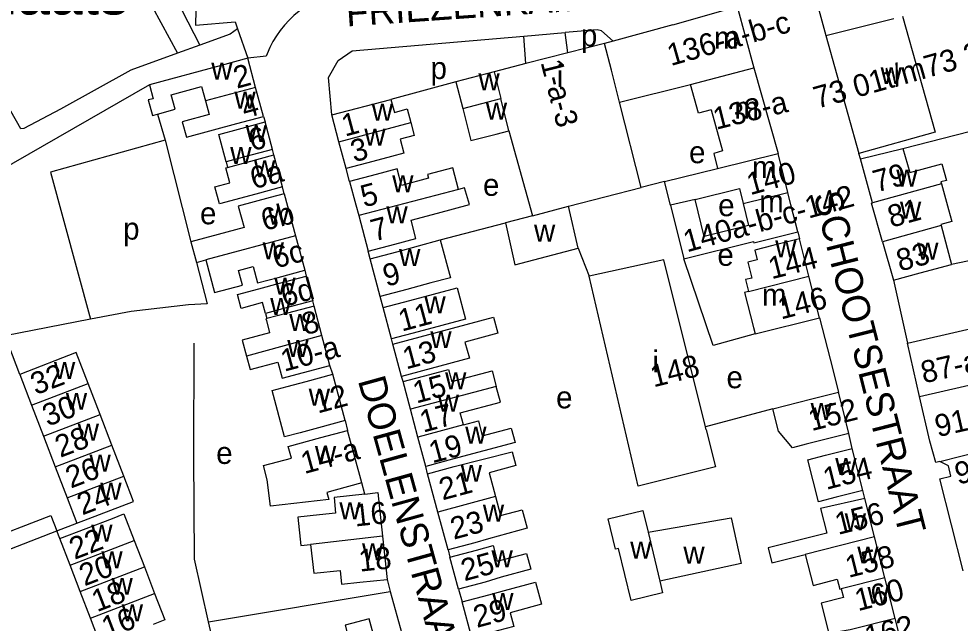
# Model space of a CAD drawing. Extents: x 159261 to 160849, y 382514 to 384534.
# Drawn here: x 159592.3 to 159763.1, y 383674.1 to 383783.7 of the extents above; entities that cross this region are included whole.
import ezdxf

# ---------------------------------------------------------------- set-up
doc = ezdxf.new("R2010")
doc.units = 0
for name, color, linetype in [('BLT_Basislijn', 7, 'Continuous'), ('BLT_Bebouwing', 7, 'Continuous'), ('BLT_Centroide', 7, 'Continuous'), ('BLT_Huisnummer', 7, 'Continuous'), ('BLT_Huisnummer_ tussenligend', 7, 'Continuous'), ('BLT_Huisnummer_reeks', 7, 'Continuous'), ('BLT_Onderdoorgang_en_onderverdeling', 7, 'Continuous'), ('BLT_Onderverdeling_panden', 7, 'Continuous'), ('BLT_Straatnaam', 7, 'Continuous'), ('BLT_Terrein_beschrifting', 7, 'Continuous')]:
    doc.layers.add(name, color=color, linetype=linetype)

msp = doc.modelspace()

# ---------------------------------------------------------------- linework, layer by layer
at = {"layer": 'BLT_Basislijn'}
for p, q in [((159631.56, 383783.16), (159631.95, 383781.91)), ((159631.95, 383781.91), (159633.83, 383776.57)), ((159683.95, 383780.59), (159691.46, 383781.26)), ((159684.27, 383775.61), (159683.95, 383780.59)), ((159691.94, 383777.56), (159691.46, 383781.26)), ((159625.16, 383778.96), (159621.07, 383777.49)), ((159637.2, 383776.98), (159633.83, 383776.57)), ((159671.62, 383772.28), (159659.82, 383769.08)), ((159616.02, 383771.76), (159555.43, 383737.07)), ((159617.49, 383766.46), (159618.85, 383761.7)), ((159636.68, 383766.03), (159636.97, 383765.02)), ((159618.85, 383761.7), (159598.02, 383755.92)), ((159618.85, 383761.7), (159623.53, 383743.27)), ((159745.03, 383758.31), (159744.75, 383759.29)), ((159598.02, 383755.92), (159605.29, 383729.24)), ((159652.31, 383754.2), (159651.68, 383756.56)), ((159640.44, 383752), (159640.14, 383753.25)), ((159709.46, 383754.23), (159705.24, 383753.14)), ((159668.75, 383743.65), (159680.58, 383746.7)), ((159733.64, 383745.1), (159733.95, 383743.83)), ((159656.04, 383740.19), (159655.71, 383741.59)), ((159773.27, 383741.61), (159761.57, 383739.18)), ((159644.17, 383738.12), (159644.42, 383737.08)), ((159751, 383736.32), (159753.55, 383724.92)), ((159658.41, 383731.34), (159657.87, 383733.36)), ((159737.57, 383729.51), (159739.51, 383721.98)), ((159592.46, 383719.24), (159589.8, 383726.24)), ((159624.03, 383704.44), (159624.09, 383724.91)), ((159660.18, 383724.73), (159659.93, 383725.66)), ((159649.27, 383719.25), (159648.76, 383720.87)), ((159739.51, 383721.98), (159741.04, 383716.02)), ((159662.02, 383717.93), (159661.75, 383718.87)), ((159729.11, 383713), (159716.91, 383709.74)), ((159651.52, 383710.84), (159651.91, 383709.07)), ((159743.51, 383705.78), (159742.94, 383708.53)), ((159666.47, 383701.22), (159666.15, 383702.53)), ((159655.06, 383697.53), (159654.53, 383699.54)), ((159745.83, 383696.7), (159745.43, 383698.17)), ((159599.2, 383690.85), (159602.83, 383692.24)), ((159586.61, 383686.01), (159599.2, 383690.85)), ((159599.75, 383689.45), (159599.2, 383690.85)), ((159670.2, 383687.38), (159670.53, 383686.06)), ((159659.12, 383682.04), (159659.71, 383679.86)), ((159626.72, 383674.34), (159659.71, 383679.86)), ((159659.71, 383679.86), (159661.77, 383672.22)), ((159672.09, 383680.26), (159672.75, 383677.95)), ((159629.57, 383662.47), (159626.72, 383674.34))]:
    msp.add_line(p, q, dxfattribs=at)
for points in [[(159593.57, 383838.89), (159614.31, 383800.04), (159625.16, 383778.96)], [(159621.07, 383777.49), (159612.6, 383774.43), (159599.83, 383767.32), (159593.2, 383763.82), (159592.64, 383763.8), (159578.88, 383788.08), (159578.47, 383789.32), (159580.38, 383790.74), (159605.05, 383805.54), (159605.98, 383805.38), (159621.07, 383777.49)], [(159624.74, 383798.83), (159624.33, 383782.58), (159631.56, 383783.16)], [(159647.32, 383787.59), (159646.21, 383787.07), (159645.15, 383786.49), (159644.12, 383785.84), (159643.14, 383785.11), (159642.21, 383784.33), (159641.33, 383783.49), (159640.5, 383782.59), (159639.74, 383781.64), (159639.05, 383780.64), (159638.41, 383779.6), (159637.85, 383778.52), (159637.37, 383777.4), (159637.2, 383776.98)], [(159631.95, 383781.91), (159630.64, 383780.98), (159625.16, 383778.96)], [(159649.08, 383766.33), (159648.52, 383773.07), (159650.27, 383776.15), (159652.81, 383777.91), (159683.95, 383780.59)], [(159700.15, 383779.66), (159698.06, 383781.54), (159697.23, 383781.74), (159691.46, 383781.26)], [(159752.73, 383760.22), (159784.09, 383768.23), (159781.95, 383775.97), (159783.82, 383776.48), (159786.45, 383777.94), (159787.98, 383780.15)], [(159693.78, 383742.14), (159695.8, 383737.05)], [(159725.91, 383726.57), (159718.32, 383724.47), (159712.99, 383740.18)], [(159624.53, 383739.56), (159626.5, 383732.04), (159623.07, 383731.83), (159612.69, 383730.67)], [(159612.69, 383730.67), (159605.29, 383729.24)], [(159605.29, 383729.24), (159589.8, 383726.24)], [(159626.72, 383674.34), (159624.2, 383685.7), (159624.03, 383704.44)], [(159585.55, 383688.82), (159598.13, 383693.65), (159599.2, 383690.85)]]:
    msp.add_lwpolyline(points, dxfattribs=at)
at = {"layer": 'BLT_Bebouwing'}
for p, q in [((159711, 383782.62), (159700.15, 383779.66)), ((159698.59, 383779.26), (159691.94, 383777.56)), ((159700.15, 383779.66), (159698.59, 383779.26)), ((159691.94, 383777.56), (159684.27, 383775.61)), ((159635.25, 383771.3), (159633.83, 383776.57)), ((159684.27, 383775.61), (159678.54, 383774.1)), ((159678.54, 383774.1), (159671.62, 383772.28)), ((159725.7, 383774.82), (159730.07, 383759.31)), ((159635.25, 383771.3), (159626.17, 383768.84)), ((159636.68, 383766.03), (159635.25, 383771.3)), ((159701.3, 383768.62), (159714.21, 383771.84)), ((159649.08, 383766.33), (159659.82, 383769.08)), ((159705.24, 383753.14), (159701.3, 383768.62)), ((159650.38, 383761.45), (159649.08, 383766.33)), ((159638.32, 383760.06), (159636.97, 383765.02)), ((159681.23, 383763.43), (159685.49, 383748.01)), ((159651.68, 383756.56), (159650.38, 383761.45)), ((159745.03, 383758.31), (159752.73, 383760.22)), ((159638.57, 383759.06), (159638.32, 383760.06)), ((159640.14, 383753.25), (159638.57, 383759.06)), ((159731.84, 383752.25), (159730.07, 383759.31)), ((159629.91, 383757.78), (159630.17, 383756.79)), ((159747.18, 383750.35), (159745.03, 383758.31)), ((159709.46, 383754.23), (159719.08, 383756.57)), ((159640.44, 383752), (159642.49, 383744.38)), ((159692.05, 383749.76), (159705.24, 383753.14)), ((159710.53, 383749.96), (159712.99, 383740.18)), ((159693.78, 383742.14), (159692.05, 383749.76)), ((159653.97, 383748.08), (159655.71, 383741.59)), ((159685.49, 383748.01), (159680.58, 383746.7)), ((159759.67, 383746.22), (159761.57, 383739.18)), ((159623.53, 383743.27), (159624.53, 383739.56)), ((159642.49, 383744.38), (159644.17, 383738.12)), ((159735.66, 383737.07), (159733.95, 383743.83)), ((159749.02, 383743.29), (159751, 383736.32)), ((159624.53, 383739.56), (159626.24, 383740.02)), ((159657.87, 383733.36), (159656.04, 383740.19)), ((159644.42, 383737.08), (159645.62, 383732.59)), ((159737.57, 383729.51), (159735.66, 383737.07)), ((159645.87, 383731.64), (159645.62, 383732.59)), ((159647.31, 383726.26), (159645.87, 383731.64)), ((159659.93, 383725.66), (159658.41, 383731.34)), ((159637.07, 383730.29), (159637.32, 383729.35)), ((159725.91, 383726.57), (159737.57, 383729.51)), ((159648.76, 383720.87), (159647.31, 383726.26)), ((159661.75, 383718.87), (159660.18, 383724.73)), ((159755.76, 383715.2), (159753.55, 383724.92)), ((159651.52, 383710.84), (159649.27, 383719.25)), ((159663.37, 383712.9), (159662.02, 383717.93)), ((159741.99, 383712.28), (159741.04, 383716.02)), ((159757.61, 383707.14), (159755.76, 383715.2)), ((159664.72, 383707.85), (159663.37, 383712.9)), ((159742.94, 383708.53), (159741.99, 383712.28)), ((159654.53, 383699.54), (159651.91, 383709.07)), ((159717.05, 383709.18), (159716.91, 383709.74)), ((159666.15, 383702.53), (159664.72, 383707.85)), ((159745.43, 383698.17), (159743.51, 383705.78)), ((159668.35, 383694.26), (159666.47, 383701.22)), ((159747.58, 383689.75), (159745.83, 383696.7)), ((159670.2, 383687.38), (159668.35, 383694.26)), ((159613.24, 383689.11), (159615.09, 383684.31)), ((159658.29, 383689.91), (159659.12, 383682.04)), ((159749.45, 383682.35), (159747.58, 383689.75)), ((159672.09, 383680.26), (159670.53, 383686.06)), ((159615.09, 383684.31), (159616.94, 383679.5)), ((159751.32, 383674.94), (159749.45, 383682.35)), ((159674.5, 383671.45), (159672.75, 383677.95)), ((159752.98, 383668.39), (159751.32, 383674.94))]:
    msp.add_line(p, q, dxfattribs=at)
for points in [[(159749.03, 383794.41), (159735.94, 383790.98), (159738.76, 383780.69)], [(159711, 383782.62), (159722.66, 383785.95), (159725.7, 383774.82)], [(159752.68, 383784.21), (159758.58, 383763.16), (159744.75, 383759.29)], [(159738.76, 383780.69), (159744.75, 383759.29)], [(159633.83, 383776.57), (159629, 383775.27), (159616.02, 383771.76)], [(159671.62, 383772.28), (159672.85, 383767.45)], [(159616.02, 383771.76), (159616.69, 383769.25), (159615.78, 383769.01), (159616.54, 383766.21), (159617.49, 383766.46)], [(159617.49, 383766.46), (159620.65, 383767.32), (159619.94, 383769.94), (159625.47, 383771.44), (159626.17, 383768.84)], [(159717.94, 383767.25), (159715.65, 383766.61), (159714.21, 383771.84)], [(159626.17, 383768.84), (159626.85, 383766.35), (159621.96, 383765.03), (159622.71, 383762.28), (159631.85, 383764.72), (159636.68, 383766.03)], [(159659.82, 383769.08), (159660.44, 383766.76), (159662.76, 383767.38), (159663.41, 383764.92)], [(159672.85, 383767.45), (159674.33, 383761.65), (159678.89, 383762.83)], [(159717.94, 383767.25), (159720.01, 383759.76), (159718.39, 383759.3)], [(159629.91, 383757.78), (159628.56, 383762.74), (159632.15, 383763.71), (159636.97, 383765.02)], [(159663.41, 383764.92), (159664.04, 383762.56), (159661.51, 383761.88), (159662.18, 383759.36), (159659.93, 383758.76), (159656.52, 383757.85), (159651.68, 383756.56)], [(159678.89, 383762.83), (159681.23, 383763.43)], [(159752.73, 383760.22), (159753.97, 383755.85), (159759.79, 383757.4), (159760.62, 383754.38), (159759.62, 383754.18), (159759.72, 383753.8)], [(159718.39, 383759.3), (159719.08, 383756.57)], [(159640.14, 383753.25), (159635.31, 383751.95), (159628.73, 383750.16), (159627.89, 383753.25), (159630.57, 383753.97), (159629.83, 383756.7), (159630.17, 383756.79)], [(159672.09, 383752.76), (159671.03, 383756.71), (159666.44, 383755.47), (159666.61, 383754.81), (159661.74, 383753.51), (159660.94, 383756.51), (159657.14, 383755.49), (159652.31, 383754.2)], [(159652.31, 383754.2), (159653.45, 383750), (159653.97, 383748.08)], [(159710.53, 383749.96), (159709.46, 383754.23)], [(159759.72, 383753.8), (159760.99, 383749.16), (159761.59, 383746.94), (159759.62, 383746.4), (159759.67, 383746.22)], [(159640.44, 383752), (159637.93, 383751.32), (159632.11, 383749.75), (159633.16, 383745.86), (159628.44, 383744.59), (159623.53, 383743.27)], [(159655.71, 383741.59), (159660.54, 383742.88), (159664.35, 383743.91), (159663.47, 383747.22), (159668.29, 383748.51), (159674.06, 383750.06), (159673.19, 383753.07), (159672.09, 383752.76)], [(159715.01, 383750.96), (159723.06, 383752.93), (159723.73, 383750.22)], [(159733.64, 383745.1), (159732.4, 383750), (159731.84, 383752.25)], [(159723.73, 383750.22), (159724.7, 383746.27), (159716.69, 383744.25), (159715.01, 383750.96)], [(159749.02, 383743.29), (159747.05, 383750.31), (159747.18, 383750.35)], [(159680.58, 383746.7), (159682.32, 383739.08), (159693.78, 383742.14)], [(159712.99, 383740.18), (159725.6, 383743.35), (159725.66, 383743.09), (159728.79, 383743.87), (159733.64, 383745.1)], [(159656.04, 383740.19), (159660.87, 383741.49), (159668.75, 383743.65)], [(159668.75, 383743.65), (159670.6, 383736.77), (159667.03, 383735.82), (159662.7, 383734.66), (159657.87, 383733.36)], [(159733.95, 383743.83), (159729.11, 383742.6), (159725.83, 383741.77), (159726.28, 383740.01), (159724.58, 383739.58), (159725.31, 383736.71), (159724.15, 383736.42), (159724.68, 383734.3)], [(159626.24, 383740.02), (159627.83, 383734.09), (159632.86, 383735.44), (159632.14, 383738.11), (159634.82, 383738.83), (159635.63, 383735.82), (159639.34, 383736.82), (159644.17, 383738.12)], [(159716.91, 383709.74), (159709.33, 383739.99), (159695.8, 383737.05)], [(159751, 383736.32), (159755.83, 383737.63), (159761.57, 383739.18)], [(159637.07, 383730.29), (159636.54, 383732.25), (159632.65, 383731.21), (159631.97, 383733.73), (159635.86, 383734.78), (159639.59, 383735.78), (159644.42, 383737.08)], [(159717.05, 383709.18), (159718.73, 383702.49), (159704.66, 383698.97), (159695.8, 383737.05)], [(159658.41, 383731.34), (159663.24, 383732.64), (159671.85, 383734.94), (159673.38, 383729.26), (159664.76, 383726.96), (159659.93, 383725.66)], [(159724.68, 383734.3), (159723.98, 383734.11), (159725.61, 383727.74), (159725.91, 383726.57)], [(159637.32, 383729.35), (159637.13, 383729.3), (159637.21, 383728.99), (159637.81, 383726.76), (159632.84, 383725.42), (159633.61, 383722.57)], [(159660.18, 383724.73), (159678.44, 383729.62), (159679.22, 383726.7), (159673.26, 383725.1), (159674.05, 383722.16), (159661.75, 383718.87)], [(159753.55, 383724.92), (159775.88, 383730.03)], [(159604.88, 383717.58), (159602.73, 383723.18), (159592.46, 383719.24)], [(159633.61, 383722.57), (159634.27, 383720.1), (159639.3, 383721.45), (159640.08, 383718.54), (159643.93, 383719.57), (159648.76, 383720.87)], [(159592.46, 383719.24), (159592.46, 383719.24), (159594.62, 383713.64)], [(159651.52, 383710.84), (159646.7, 383709.55), (159643.34, 383708.64), (159640.53, 383707.89), (159638.27, 383716.3), (159641, 383717.03), (159644.44, 383717.96), (159649.27, 383719.25)], [(159662.02, 383717.93), (159666.85, 383719.23), (159670.27, 383720.14), (159670.86, 383717.95), (159678.16, 383719.9), (159678.92, 383717.06)], [(159607.04, 383711.98), (159604.88, 383717.58)], [(159672.96, 383710.06), (159672.37, 383712.26), (159679.68, 383714.22), (159678.92, 383717.06)], [(159729.11, 383713), (159736.2, 383714.8), (159741.04, 383716.02)], [(159594.62, 383713.64), (159596.77, 383708.04)], [(159732.68, 383705.93), (159730.14, 383708.92), (159729.11, 383713)], [(159609.19, 383706.38), (159607.04, 383711.98)], [(159672.96, 383710.06), (159675.68, 383710.79), (159676.4, 383708.08), (159681.64, 383709.49), (159682.34, 383706.87), (159670.98, 383703.83), (159666.15, 383702.53)], [(159654.53, 383699.54), (159649.71, 383698.22), (159648.2, 383697.81), (159648.55, 383696.53), (159637.95, 383695.34), (159637.39, 383700.08), (159636.69, 383702.69), (159641.75, 383704.05), (159641.18, 383706.18), (159647.08, 383707.77), (159651.91, 383709.07)], [(159596.77, 383708.04), (159598.92, 383702.44)], [(159742.94, 383708.53), (159738.1, 383707.3), (159735.15, 383706.55), (159732.68, 383705.93)], [(159759.42, 383703.42), (159758.7, 383703.24), (159757.61, 383707.14)], [(159611.34, 383700.78), (159609.19, 383706.38)], [(159745.43, 383698.17), (159740.59, 383696.94), (159737.4, 383696.14), (159735.47, 383703.75), (159738.66, 383704.56), (159743.51, 383705.78)], [(159666.47, 383701.22), (159671.3, 383702.52), (159681.8, 383705.21), (159682.48, 383702.68), (159677.64, 383701.38), (159678.8, 383697.07)], [(159598.92, 383702.44), (159601.07, 383696.84)], [(159763.65, 383683.59), (159759.43, 383700.31), (159761.45, 383700.79), (159760.99, 383702.63), (159759.42, 383703.42)], [(159602.83, 383692.24), (159613.1, 383696.18), (159611.34, 383700.78)], [(159655.06, 383697.53), (159649.49, 383696.93), (159649.79, 383694.08), (159646.87, 383693.78), (159642.93, 383693.34), (159643.5, 383688.17), (159645.22, 383688.38)], [(159655.06, 383697.53), (159657.45, 383697.78), (159658.29, 383689.91)], [(159678.8, 383697.07), (159679.72, 383693.63), (159683.62, 383694.68), (159684.53, 383691.31), (159677.54, 383689.41), (159675.02, 383688.68), (159670.2, 383687.38)], [(159601.07, 383696.84), (159602.83, 383692.24)], [(159745.83, 383696.7), (159737.77, 383694.91), (159738.9, 383690.41), (159728.27, 383687.75)], [(159599.75, 383689.45), (159609.27, 383693.11), (159611.38, 383693.92), (159613.24, 383689.11)], [(159699.26, 383693.02), (159705.54, 383694.53), (159706.49, 383690.62)], [(159708.63, 383681.7), (159709.09, 383679.59), (159703.44, 383678.24), (159701.13, 383687.65), (159700.59, 383687.52), (159699.26, 383693.02)], [(159706.49, 383690.62), (159721.55, 383693.24), (159723.37, 383684.92), (159708.63, 383681.7)], [(159601.59, 383684.64), (159599.75, 383689.45)], [(159645.22, 383688.38), (159645.8, 383683.16), (159650.59, 383683.69), (159650.85, 383681.17), (159654.15, 383681.52), (159659.12, 383682.04)], [(159670.53, 383686.06), (159675.36, 383687.36), (159678.36, 383688.17), (159679.12, 383685.34), (159684.43, 383686.77), (159685.21, 383683.88), (159679.85, 383682.43), (159676.92, 383681.56), (159672.09, 383680.26)], [(159728.27, 383687.75), (159728.94, 383685.07), (159734.99, 383686.58)], [(159734.99, 383686.58), (159736.41, 383680.96), (159740.81, 383682.08), (159741.26, 383680.28), (159741.52, 383680.35)], [(159603.44, 383679.84), (159601.59, 383684.64)], [(159672.75, 383677.95), (159677.58, 383679.25), (159680.41, 383680.01), (159686.05, 383681.52), (159687.12, 383677.53), (159681.47, 383676.01), (159682.14, 383673.51), (159679.33, 383672.75), (159674.5, 383671.45)], [(159605.28, 383675.03), (159603.44, 383679.84)], [(159741.52, 383680.35), (159741.92, 383678.75), (159737.9, 383677.74), (159739.29, 383672.23)], [(159616.94, 383679.5), (159618.79, 383674.7), (159616.65, 383673.88)], [(159607.13, 383670.22), (159605.28, 383675.03)], [(159661.77, 383672.22), (159656.94, 383670.91), (159655.85, 383674.89), (159651.49, 383673.72), (159652.56, 383669.71), (159645.96, 383667.92)]]:
    msp.add_lwpolyline(points, dxfattribs=at)
at = {"layer": 'BLT_Onderdoorgang_en_onderverdeling'}
for points in [[(159638.32, 383760.06), (159633.49, 383758.75), (159629.91, 383757.78)], [(159630.17, 383756.79), (159633.74, 383757.76), (159638.57, 383759.06)], [(159645.62, 383732.59), (159640.79, 383731.29), (159637.07, 383730.29)], [(159645.87, 383731.64), (159641.04, 383730.35), (159637.32, 383729.35)]]:
    msp.add_lwpolyline(points, dxfattribs=at)
at = {"layer": 'BLT_Onderverdeling_panden'}
for p, q in [((159678.54, 383774.1), (159679.76, 383769.3)), ((159714.21, 383771.84), (159725.7, 383774.82)), ((159672.85, 383767.45), (159679.76, 383769.3)), ((159681.23, 383763.43), (159679.76, 383769.3)), ((159650.38, 383761.45), (159663.41, 383764.92)), ((159719.08, 383756.57), (159730.07, 383759.31)), ((159759.72, 383753.8), (159747.18, 383750.35)), ((159672.09, 383752.76), (159653.97, 383748.08)), ((159723.73, 383750.22), (159731.84, 383752.25)), ((159715.01, 383750.96), (159710.53, 383749.96)), ((159685.49, 383748.01), (159692.05, 383749.76)), ((159759.67, 383746.22), (159749.02, 383743.29)), ((159642.49, 383744.38), (159626.24, 383740.02)), ((159724.68, 383734.3), (159735.66, 383737.07)), ((159647.31, 383726.26), (159633.61, 383722.57)), ((159594.62, 383713.64), (159604.88, 383717.58)), ((159678.92, 383717.06), (159663.37, 383712.9)), ((159596.77, 383708.04), (159607.04, 383711.98)), ((159672.96, 383710.06), (159664.72, 383707.85)), ((159598.92, 383702.44), (159609.19, 383706.38)), ((159759.42, 383703.42), (159770.98, 383706.35)), ((159601.07, 383696.84), (159611.34, 383700.78)), ((159678.8, 383697.07), (159668.35, 383694.26)), ((159706.49, 383690.62), (159708.63, 383681.7)), ((159601.59, 383684.64), (159613.24, 383689.11)), ((159658.29, 383689.91), (159645.22, 383688.38)), ((159747.58, 383689.75), (159734.99, 383686.58)), ((159603.44, 383679.84), (159615.09, 383684.31)), ((159749.45, 383682.35), (159741.52, 383680.35)), ((159605.28, 383675.03), (159616.94, 383679.5))]:
    msp.add_line(p, q, dxfattribs=at)
for points in [[(159738.76, 383780.69), (159751.09, 383783.78)], [(159701.3, 383768.62), (159699.83, 383774.41), (159698.59, 383779.26)], [(159755.76, 383715.2), (159767.58, 383717.96), (159767.88, 383716.44)], [(159751.32, 383674.94), (159743.13, 383672.87), (159739.29, 383672.23)]]:
    msp.add_lwpolyline(points, dxfattribs=at)

# ---------------------------------------------------------------- texts
at = {"layer": 'BLT_Centroide'}
for s, p in [('p', (159694.3, 383778.74)), ('m', (159718.45, 383778.34)), ('w', (159627.21, 383772.72)), ('p', (159667.01, 383772.81)), ('i', (159689.92, 383771.34)), ('w', (159675.69, 383770.78)), ('w', (159748.67, 383771.89)), ('w', (159631.42, 383767.44)), ('m', (159722.14, 383765.62)), ('w', (159656.34, 383765.25)), ('w', (159677.04, 383765.47)), ('w', (159633.44, 383761.41)), ('w', (159654.99, 383760.75)), ('w', (159630.66, 383757.39)), ('e', (159713.92, 383757.54)), ('w', (159634.98, 383754.97)), ('m', (159725.35, 383754.84)), ('w', (159660.05, 383752.28)), ('w', (159751.52, 383753.31)), ('e', (159676.53, 383751.62)), ('m', (159726.65, 383748.65)), ('e', (159719.2, 383747.93)), ('w', (159752.19, 383747.51)), ('e', (159625.18, 383746.46)), ('w', (159637.48, 383746.41)), ('w', (159658.99, 383746.62)), ('p', (159611.23, 383743.68)), ('w', (159685.78, 383743.34)), ('w', (159636.53, 383740.09)), ('w', (159729.55, 383740.46)), ('w', (159755.31, 383740.05)), ('w', (159661.3, 383738.88)), ('e', (159719.06, 383738.93)), ('w', (159638.66, 383733.69)), ('m', (159727.15, 383731.69)), ('w', (159637.91, 383730.03)), ('w', (159665.89, 383730.31)), ('w', (159641.37, 383727.09)), ('w', (159666.97, 383724)), ('w', (159641, 383722.41)), ('i', (159707.27, 383719.58)), ('w', (159598.67, 383718.41)), ('w', (159669.65, 383716.53)), ('e', (159720.71, 383716.72)), ('w', (159600.83, 383712.81)), ('w', (159644.9, 383713.56)), ('e', (159689.79, 383713.07)), ('w', (159668.3, 383712.47)), ('w', (159735.98, 383710.97)), ('w', (159602.98, 383707.22)), ('w', (159673.3, 383706.66)), ('e', (159628.11, 383702.99)), ('w', (159646.03, 383703.19)), ('w', (159605.12, 383701.59)), ('w', (159740.45, 383700.97)), ('w', (159672.48, 383699.75)), ('w', (159607.08, 383696.5)), ('w', (159650.46, 383692.97)), ('w', (159676.5, 383692.53)), ('w', (159742.17, 383690.94)), ('w', (159605.43, 383688.88)), ('w', (159654.57, 383685.53)), ('w', (159703.24, 383685.82)), ('w', (159607.27, 383684.06)), ('w', (159678.07, 383684.22)), ('w', (159712.89, 383684.92)), ('w', (159744.44, 383684.94)), ('w', (159609.12, 383679.25)), ('w', (159746.29, 383677.62)), ('w', (159678.2, 383676.5)), ('w', (159610.97, 383674.44))]:
    msp.add_text(s, height=4, dxfattribs=at).set_placement(p)
at = {"layer": 'BLT_Huisnummer'}
for s, rotation, p in [('2', 15.1397, (159631.85, 383771.04)), ('4', 15.1425, (159633.29, 383765.62)), ('1', 14.9034, (159651.48, 383762.35)), ('6', 15.1425, (159634.63, 383759.7)), ('6a', 15.0341, (159634.89, 383752.8)), ('79', 15.1617, (159747.91, 383752.22)), ('5', 15.0089, (159654.93, 383749.5)), ('6b', 15.037, (159636.87, 383745.23)), ('6c', 15.0381, (159638.91, 383738.41)), ('9', 14.9978, (159658.98, 383735.11)), ('6d', 15.037, (159640.47, 383731.46)), ('146', 14.1715, (159730.6, 383729.18)), ('8', 15.3694, (159644.28, 383726.32)), ('13', 14.9942, (159662.57, 383720.12)), ('148', 14.0583, (159707.47, 383716.86)), ('32', 21.0019, (159595.37, 383715.44)), ('12', 15.037, (159646.54, 383712.12)), ('17', 15.053, (159665.67, 383708.65)), ('152', 14.2283, (159736.15, 383708.93)), ('28', 21.0019, (159599.82, 383704.08)), ('154', 14.1836, (159738.82, 383698.28)), ('21', 14.9942, (159669.17, 383696.37)), ('24', 21.0019, (159603.81, 383693.64)), ('16', 6.0563, (159653.35, 383691.63)), ('22', 21.0019, (159602.4, 383685.58)), ('18', 6.0633, (159654.17, 383683.44)), ('25', 15.0561, (159673.14, 383681.69)), ('158', 14.1777, (159742.86, 383682.3)), ('18', 21.0019, (159606.47, 383676.07)), ('162', 14.1761, (159746.37, 383669.62))]:
    msp.add_text(s, height=4, rotation=rotation, dxfattribs=at).set_placement(p)
at = {"layer": 'BLT_Huisnummer_ tussenligend'}
for s, rotation, p in [('3', 14.9034, (159653.11, 383757.69)), ('140', 15.4074, (159725.02, 383751.72)), ('81', 15.1617, (159750.59, 383745.83)), ('7', 15.0089, (159656.77, 383743.31)), ('83', 15.1617, (159752.17, 383737.87)), ('144', 14.1805, (159728.89, 383736.47)), ('11', 14.9978, (159661.79, 383726.98)), ('15', 14.9942, (159664.43, 383713.93)), ('30', 21.0019, (159597.53, 383709.73)), ('19', 15.053, (159667.33, 383703.08)), ('26', 21.0019, (159601.73, 383698.5)), ('156', 14.1836, (159740.97, 383690.1)), ('23', 14.9942, (159671.21, 383689.24)), ('20', 21.0019, (159604.21, 383680.77)), ('160', 14.1777, (159744.57, 383676.27)), ('29', 15.0561, (159675.4, 383673.23)), ('16', 21.0019, (159608.29, 383671.26))]:
    msp.add_text(s, height=4, rotation=rotation, dxfattribs=at).set_placement(p)
at = {"layer": 'BLT_Huisnummer_reeks'}
for s, rotation, p in [('136-a-b-c', 15.9194, (159710.61, 383775.15)), ('73 01t/m73 29', 15.6501, (159737.15, 383767.4)), ('1-a-3', 284.2737, (159686.96, 383775.84)), ('138-a', 14.0424, (159718.84, 383763.59)), ('140a-b-c-142', 15.5029, (159713.53, 383741.35)), ('87-a t/m 89', 12.8885, (159756.49, 383717.58)), ('10-a', 15.0362, (159640.44, 383719.7)), ('91-a-b', 12.8922, (159759.03, 383707.83)), ('93 t/m k', 13.9705, (159762.71, 383699.2)), ('14-a', 15.3677, (159644.11, 383701.14))]:
    msp.add_text(s, height=4, rotation=rotation, dxfattribs=at).set_placement(p)
at = {"layer": 'BLT_Straatnaam'}
for s, height, rotation, p in [('FRIEZENKAMPSTRAAT', 5, 3.9033, (159651.8, 383782.34)), ('SCHOOTSESTRAAT', 4.9999, 284.1745, (159736.47, 383751.8)), ('DOELENSTRAAT', 5, 285.4609, (159653.79, 383718.14))]:
    msp.add_text(s, height=height, rotation=rotation, dxfattribs=at).set_placement(p)
at = {"layer": 'BLT_Terrein_beschrifting'}
msp.add_text('Begraafplaats', height=8, dxfattribs=at).set_placement((159546.2, 383784.52))

doc.saveas('drawing.dxf')
